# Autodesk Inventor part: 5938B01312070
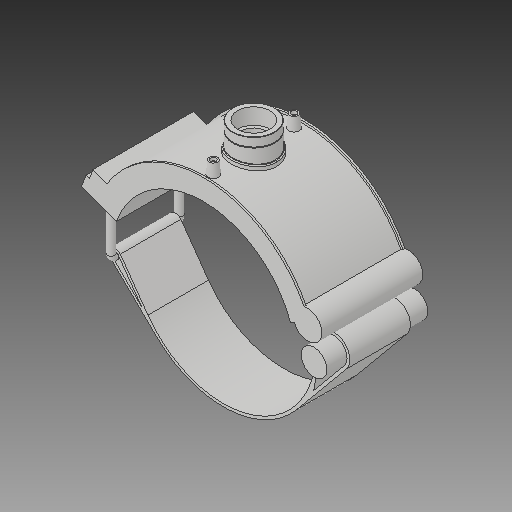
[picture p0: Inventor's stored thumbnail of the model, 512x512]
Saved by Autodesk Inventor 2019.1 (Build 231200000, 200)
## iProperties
Created: 2017-07
Part Number: 5938B01312070
Material: Generic
Description: PLASSON TRANSITION SADDLE 12''IPS x 2"NPT
Document SubType Name: Modeling
Designer: KIM
Density: 1 g/cm^3
Appearance: Default
Author: KIM
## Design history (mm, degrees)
derived "5938B.ipt"
feature "Solid1::5938B.ipt"
tag "TaggingFeature1"
body "Solid1"
other parameters: "d0" = 323.4, "d1" = 388.08, "d2" = 487.045, "d3" = 80.85, "d4" = 176.022, "d5" = 0, "d40" = 201.8016, "d41" = 79.3184, "d43" = 0, "d45" = 0, "d47" = 240.776, "d48" = 73.6528, "d50" = 0, "d78" = 216.04, "d79" = 15, "d80" = 70.4088, "d82" = 5 deg, "d84" = 4, "d85" = 14, "d86" = 0, "d87" = 3, "d88" = 0, "d96" = 395.8416, "d97" = 3.52044, "d98" = 0, "d102" = 1.69968, "d103" = 56.656, "d104" = 28.0416, "d105" = 0, "d106" = 45.3248, "d108" = 0, "d109" = -15.57867, "d111" = 0.5, "d112" = 0.5, "d113" = 0, "d114" = 0.5, "d117" = 0.56656, "d120" = 140 deg, "d121" = 24.228, "d122" = 20 deg, "d123" = 1552.32, "d124" = 232.848, "d126" = 0, "d143" = 333.102, "d145" = 49.75385, "d149" = 4.851, "d150" = 54.72923, "d153" = 176.022, "d154" = 0, "d156" = 194.04, "d157" = 160 deg, "d159" = 12.936, "d161" = 4.851, "d162" = 105.6132, "d163" = 0, "d164" = 161.7, "d167" = 32.34, "d168" = 189.30732, "d170" = 4.851, "d172" = 0, "d173" = 1, "d175" = 161.7, "d176" = 20 deg, "d177" = 22.638, "d178" = 64.68, "d180" = 0, "d183" = 25.872, "d184" = 18.1104, "d185" = 57.20715, "d186" = 57.20715, "d187" = 194.04, "d188" = 19.404, "d189" = 22.638, "d190" = 0, "d191" = 232.848, "d193" = 12.936, "d194" = 6.6297, "d195" = 90 deg, "d197" = 0, "d199" = 0, "d_" = 323.4, "B_" = 194.818, "H_" = 46.736, "L_" = 176.022, "d_t" = 6, "G_" = 56.656, "d148" = 4.851, "d160" = 4.851, "d169" = 4.851, "d192" = 12.936
